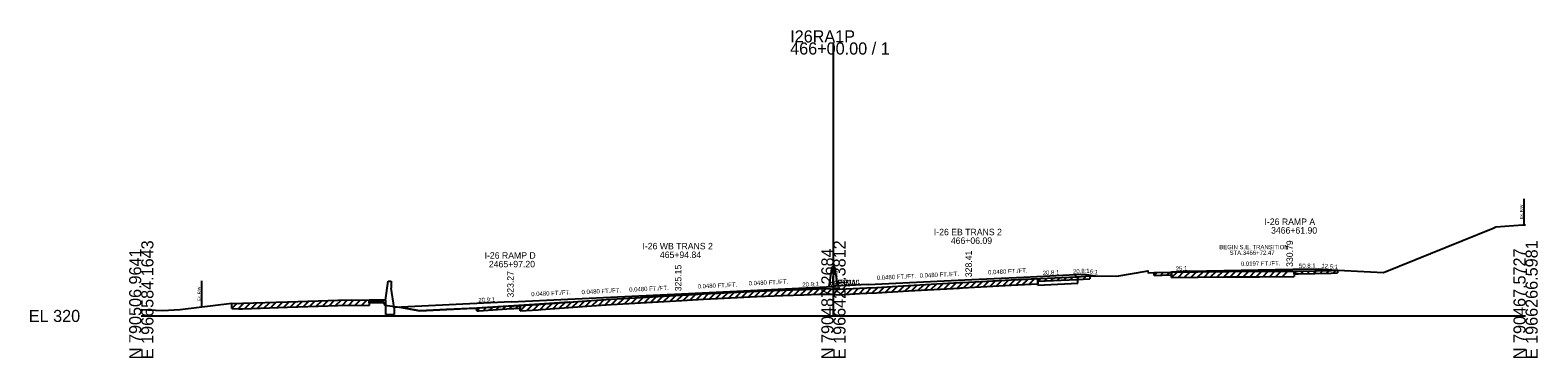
# Model space of a CAD drawing. Extents: x -44 to 4323, y -10 to 9601.
# Drawn here: x 3974.3 to 4322.8, y 4490.3 to 4566.1 of the extents above; entities that cross this region are included whole.
import ezdxf

# ---------------------------------------------------------------- set-up
doc = ezdxf.new("R2010")
doc.units = 0
for name, color, linetype in [('1', 7, 'Continuous'), ('DateStamp', 7, 'Continuous'), ('NotForConst', 7, 'Continuous'), ('QCQA', 7, 'Continuous'), ('RD_SHT_Bndy', 7, 'Continuous'), ('RD_SHT_Iplotshp', 7, 'Continuous'), ('RD_SHT_TX', 7, 'Continuous'), ('RD_XS_ExGround', 7, 'Continuous'), ('RD_XS_ExPaveRet', 7, 'Continuous'), ('RD_XS_MatchLine', 7, 'Continuous'), ('RD_XS_MedBWall', 7, 'Continuous'), ('RD_XS_Misc_Line', 7, 'Continuous'), ('RD_XS_Pave', 7, 'Continuous'), ('RD_XS_PaveOvlay', 7, 'Continuous'), ('RD_XS_PaveShd', 7, 'Continuous'), ('RD_XS_TX_Elev_PR', 7, 'Continuous'), ('RD_XS_TX_Profile', 7, 'Continuous'), ('RD_XS_TX_ShdSlope', 7, 'Continuous'), ('RD_XS_TX_Slope', 7, 'Continuous'), ('seal', 7, 'Continuous'), ('TR SN EXTRUDED PANEL SIGNS - GROUND MOUNTED', 7, 'Continuous')]:
    doc.layers.add(name, color=color, linetype=linetype)

msp = doc.modelspace()

# ---------------------------------------------------------------- linework, layer by layer
at = {"layer": 'DateStamp'}
msp.add_lwpolyline([(4000, 4501.48), (4004.93, 4501.29), (4008.98, 4501.5), (4020.9, 4502.96), (4022.54, 4502.9), (4023.4, 4502.92), (4033.79, 4503.26), (4040.87, 4503.5), (4045.42, 4503.65), (4048.7, 4503.71), (4052.67, 4503.67), (4052.81, 4503.38), (4053.89, 4503.38), (4055.81, 4503.38), (4056.28, 4502.5), (4059.72, 4502.01), (4064.36, 4501.2), (4076.82, 4501.77), (4077.57, 4501.81), (4077.99, 4501.84), (4085.55, 4502.33), (4086.14, 4502.37), (4091.71, 4502.66), (4092.46, 4502.72), (4104.11, 4503.6), (4108.61, 4503.86), (4116.78, 4504.33), (4124.99, 4504.81), (4129.94, 4505.1), (4133.18, 4505.27), (4142.32, 4505.76), (4148.34, 4505.96), (4153.18, 4506.13), (4156.64, 4506.25), (4158.63, 4506.32), (4160, 4506.23), (4160.47, 4506.2), (4161.4, 4506.16), (4166.11, 4506.41), (4167.71, 4506.49), (4169.93, 4506.61), (4177.32, 4507.04), (4189.15, 4507.7), (4189.54, 4507.72), (4189.86, 4507.74), (4201.12, 4508.35), (4216.25, 4509.08), (4219.26, 4509.24), (4220.2, 4509.24), (4225.54, 4509.22), (4232.29, 4510.35), (4232.65, 4510.4), (4232.75, 4509.95), (4234.16, 4510.02), (4237.94, 4510.15), (4250.58, 4510.3), (4251.4, 4510.31), (4258.46, 4510.33), (4267.49, 4510.35), (4275.04, 4510.53), (4276.5, 4510.56), (4278.11, 4510.49), (4287.16, 4510.04), (4312.48, 4520.33), (4313.09, 4520.58), (4319.34, 4521.07), (4320, 4521.09)], dxfattribs=at)
at = {"layer": 'NotForConst'}
for p, q in [((4234.16, 4509.39), (4234.81, 4510.04)), ((4235.66, 4509.44), (4236.31, 4510.09)), ((4237.16, 4509.5), (4237.81, 4510.14)), ((4238.16, 4508.9), (4239.43, 4510.16)), ((4239.67, 4508.92), (4240.94, 4510.18)), ((4241.17, 4508.94), (4242.45, 4510.2)), ((4242.68, 4508.96), (4243.95, 4510.22)), ((4244.19, 4508.97), (4245.46, 4510.24)), ((4245.7, 4508.99), (4246.97, 4510.26)), ((4247.2, 4509.01), (4248.48, 4510.28)), ((4248.71, 4509.03), (4249.98, 4510.3)), ((4250.22, 4509.05), (4251.49, 4510.31)), ((4251.73, 4509.07), (4252.99, 4510.32)), ((4253.23, 4509.07), (4254.49, 4510.32)), ((4254.74, 4509.07), (4256, 4510.32)), ((4256.25, 4509.07), (4257.51, 4510.33)), ((4257.76, 4509.08), (4259.02, 4510.33)), ((4259.26, 4509.08), (4260.52, 4510.33)), ((4260.77, 4509.08), (4262.03, 4510.34)), ((4262.28, 4509.09), (4263.54, 4510.34)), ((4263.79, 4509.09), (4265.05, 4510.34)), ((4266.5, 4509.72), (4267.12, 4510.35)), ((4268, 4509.74), (4268.64, 4510.38)), ((4269.5, 4509.77), (4270.14, 4510.41)), ((4271, 4509.81), (4271.64, 4510.45)), ((4272.5, 4509.84), (4273.14, 4510.48)), ((4274, 4509.88), (4274.64, 4510.52)), ((4275.5, 4509.91), (4276.15, 4510.55)), ((4167.48, 4505.23), (4168.81, 4506.55)), ((4168.99, 4505.31), (4170.32, 4506.64)), ((4170.49, 4505.4), (4171.83, 4506.72)), ((4172, 4505.48), (4173.33, 4506.81)), ((4173.51, 4505.57), (4174.84, 4506.89)), ((4175.02, 4505.65), (4176.35, 4506.98)), ((4176.52, 4505.74), (4177.86, 4507.07)), ((4178.03, 4505.83), (4179.36, 4507.15)), ((4179.54, 4505.91), (4180.87, 4507.23)), ((4181.05, 4505.99), (4182.38, 4507.32)), ((4182.55, 4506.08), (4183.88, 4507.4)), ((4184.06, 4506.16), (4185.39, 4507.49)), ((4185.57, 4506.25), (4186.9, 4507.57)), ((4187.08, 4506.33), (4188.41, 4507.66)), ((4188.58, 4506.42), (4189.91, 4507.74)), ((4190.09, 4506.5), (4191.42, 4507.82)), ((4191.6, 4506.58), (4192.93, 4507.9)), ((4193.11, 4506.66), (4194.43, 4507.98)), ((4194.61, 4506.74), (4195.94, 4508.07)), ((4196.12, 4506.83), (4197.45, 4508.15)), ((4197.63, 4506.91), (4198.96, 4508.23)), ((4199.14, 4506.99), (4200.46, 4508.31)), ((4200.64, 4507.07), (4201.97, 4508.39)), ((4202.15, 4507.15), (4203.47, 4508.46)), ((4203.66, 4507.22), (4204.98, 4508.53)), ((4205.17, 4507.29), (4206.49, 4508.61)), ((4207.26, 4508.02), (4207.92, 4508.68)), ((4208.76, 4508.09), (4209.42, 4508.75)), ((4210.26, 4508.17), (4210.92, 4508.82)), ((4211.76, 4508.24), (4212.42, 4508.9)), ((4213.26, 4508.31), (4213.92, 4508.97)), ((4214.76, 4508.39), (4215.42, 4509.04)), ((4216.26, 4508.46), (4216.92, 4509.12)), ((4217.77, 4508.53), (4218.43, 4509.19)), ((4026.9, 4501.79), (4028.2, 4503.08)), ((4028.4, 4501.84), (4029.7, 4503.13)), ((4029.9, 4501.89), (4031.2, 4503.18)), ((4031.41, 4501.93), (4032.7, 4503.23)), ((4032.91, 4501.98), (4034.2, 4503.28)), ((4034.41, 4502.03), (4035.7, 4503.33)), ((4035.91, 4502.08), (4037.2, 4503.38)), ((4037.41, 4502.14), (4038.7, 4503.43)), ((4038.91, 4502.19), (4040.2, 4503.48)), ((4040.41, 4502.24), (4041.7, 4503.53)), ((4041.91, 4502.29), (4043.2, 4503.58)), ((4043.41, 4502.34), (4044.7, 4503.63)), ((4044.91, 4502.39), (4046.19, 4503.67)), ((4046.41, 4502.42), (4047.68, 4503.69)), ((4047.91, 4502.45), (4049.17, 4503.71)), ((4049.41, 4502.46), (4050.65, 4503.69)), ((4050.91, 4502.44), (4052.15, 4503.68)), ((4096.63, 4501.78), (4097.99, 4503.14)), ((4098.13, 4501.9), (4099.49, 4503.25)), ((4099.64, 4502.01), (4101, 4503.37)), ((4101.15, 4502.13), (4102.51, 4503.48)), ((4102.66, 4502.24), (4104.02, 4503.6)), ((4104.16, 4502.36), (4105.5, 4503.68)), ((4105.67, 4502.44), (4107, 4503.77)), ((4107.18, 4502.53), (4108.51, 4503.86)), ((4108.69, 4502.62), (4110.02, 4503.94)), ((4110.19, 4502.7), (4111.53, 4504.03)), ((4111.7, 4502.79), (4113.04, 4504.12)), ((4113.21, 4502.88), (4114.54, 4504.21)), ((4114.72, 4502.97), (4116.05, 4504.29)), ((4116.22, 4503.05), (4117.56, 4504.38)), ((4117.73, 4503.14), (4119.07, 4504.47)), ((4119.24, 4503.23), (4120.57, 4504.55)), ((4120.75, 4503.31), (4122.08, 4504.64)), ((4122.25, 4503.4), (4123.59, 4504.73)), ((4123.76, 4503.49), (4125.1, 4504.82)), ((4125.27, 4503.58), (4126.6, 4504.9)), ((4126.78, 4503.66), (4128.11, 4504.99)), ((4128.28, 4503.75), (4129.62, 4505.08)), ((4129.79, 4503.84), (4131.12, 4505.16)), ((4131.3, 4503.92), (4132.63, 4505.24)), ((4132.81, 4504), (4134.13, 4505.32)), ((4134.31, 4504.08), (4135.64, 4505.4)), ((4135.82, 4504.16), (4137.15, 4505.49)), ((4137.33, 4504.24), (4138.66, 4505.57)), ((4138.84, 4504.33), (4140.16, 4505.65)), ((4140.34, 4504.41), (4141.67, 4505.73)), ((4141.85, 4504.49), (4143.16, 4505.79)), ((4143.36, 4504.55), (4144.66, 4505.84)), ((4144.87, 4504.6), (4146.17, 4505.89)), ((4146.37, 4504.65), (4147.67, 4505.94)), ((4147.88, 4504.7), (4149.18, 4505.99)), ((4149.39, 4504.75), (4150.69, 4506.04)), ((4150.9, 4504.8), (4152.2, 4506.1)), ((4152.4, 4504.85), (4153.71, 4506.15)), ((4153.91, 4504.91), (4155.21, 4506.2)), ((4155.42, 4504.96), (4156.72, 4506.26)), ((4156.93, 4505.01), (4158.22, 4506.3)), ((4158.43, 4505.06), (4159.63, 4506.25)), ((4159.94, 4504.99), (4161.13, 4506.17)), ((4161.45, 4504.91), (4162.78, 4506.23)), ((4162.96, 4504.99), (4164.28, 4506.31)), ((4164.46, 4505.07), (4165.79, 4506.39)), ((4165.97, 4505.15), (4167.29, 4506.47)), ((4020.9, 4501.71), (4022.11, 4502.91)), ((4022.4, 4501.65), (4023.68, 4502.93)), ((4023.9, 4501.69), (4025.2, 4502.98)), ((4025.4, 4501.74), (4026.7, 4503.03)), ((4077.57, 4501.19), (4078.24, 4501.85)), ((4079.07, 4501.28), (4079.74, 4501.95)), ((4080.57, 4501.38), (4081.24, 4502.05)), ((4082.07, 4501.48), (4082.74, 4502.15)), ((4083.57, 4501.58), (4084.24, 4502.25)), ((4085.07, 4501.68), (4085.74, 4502.34)), ((4086.58, 4501.77), (4087.24, 4502.43)), ((4087.58, 4501.2), (4088.91, 4502.51)), ((4089.09, 4501.27), (4090.41, 4502.59)), ((4090.6, 4501.35), (4091.93, 4502.68)), ((4092.1, 4501.44), (4093.46, 4502.79)), ((4093.61, 4501.55), (4094.97, 4502.91)), ((4095.12, 4501.67), (4096.48, 4503.02))]:
    msp.add_line(p, q, dxfattribs=at)
at = {"layer": 'QCQA'}
for p, q in [((4167.71, 4506.49), (4169.93, 4506.61)), ((4169.93, 4506.61), (4177.32, 4507.04)), ((4177.32, 4507.04), (4189.15, 4507.7)), ((4189.15, 4507.7), (4189.54, 4507.72)), ((4189.54, 4507.72), (4189.86, 4507.74)), ((4189.86, 4507.74), (4201.12, 4508.35)), ((4201.12, 4508.35), (4207.26, 4508.65)), ((4099, 4503.22), (4092.09, 4502.69)), ((4099, 4503.22), (4104.11, 4503.6)), ((4104.11, 4503.6), (4108.61, 4503.86)), ((4108.61, 4503.86), (4116.78, 4504.33)), ((4116.78, 4504.33), (4124.99, 4504.81)), ((4124.99, 4504.81), (4129.94, 4505.1)), ((4129.94, 4505.1), (4133.18, 4505.27)), ((4133.18, 4505.27), (4142.32, 4505.76)), ((4142.32, 4505.76), (4148.34, 4505.96)), ((4148.34, 4505.96), (4153.18, 4506.13)), ((4153.18, 4506.13), (4156.64, 4506.25)), ((4156.64, 4506.25), (4158.63, 4506.32)), ((4158.63, 4506.32), (4160, 4506.23)), ((4160, 4506.23), (4160.47, 4506.2)), ((4160.47, 4506.2), (4161.4, 4506.16)), ((4161.4, 4506.16), (4166.11, 4506.41)), ((4166.11, 4506.41), (4167.71, 4506.49)), ((4064.36, 4501.2), (4059.6, 4502.02)), ((4070.59, 4501.48), (4064.36, 4501.2)), ((4077.57, 4501.82), (4070.59, 4501.48)), ((4086.14, 4502.37), (4077.57, 4501.82)), ((4092.09, 4502.69), (4086.14, 4502.37))]:
    msp.add_line(p, q, dxfattribs=at)
at = {"layer": 'RD_SHT_Bndy'}
for p, q in [((4160, 4500), (4160, 4563.26)), ((4000, 4500), (4160, 4500)), ((4160, 4500), (4320, 4500))]:
    msp.add_line(p, q, dxfattribs=at)
at = {"layer": 'RD_SHT_Iplotshp'}
for p, q in [((4234.16, 4509.39), (4234.16, 4510.02)), ((4238.16, 4508.9), (4238.16, 4510.15)), ((4238.16, 4510.15), (4238.16, 4509.52)), ((4266.5, 4510.35), (4266.5, 4509.1)), ((4266.5, 4509.72), (4266.5, 4510.35)), ((4276.5, 4510.56), (4276.5, 4509.94)), ((4189.86, 4506.49), (4201.12, 4507.1)), ((4201.12, 4507.1), (4207.26, 4507.4)), ((4207.26, 4508.65), (4207.26, 4507.4)), ((4207.26, 4508.02), (4207.26, 4508.65)), ((4207.26, 4508.02), (4216.25, 4508.46)), ((4216.25, 4508.46), (4219.26, 4508.61)), ((4219.26, 4509.24), (4219.26, 4508.61)), ((4234.16, 4509.39), (4237.94, 4509.52)), ((4237.94, 4509.52), (4238.16, 4509.52)), ((4238.16, 4508.9), (4250.58, 4509.05)), ((4250.58, 4509.05), (4251.4, 4509.06)), ((4251.4, 4509.06), (4258.46, 4509.08)), ((4258.46, 4509.08), (4266.5, 4509.1)), ((4266.5, 4509.72), (4267.49, 4509.72)), ((4267.49, 4509.72), (4275.04, 4509.9)), ((4275.04, 4509.9), (4276.5, 4509.94)), ((4052.67, 4503.67), (4052.67, 4502.42)), ((4108.61, 4502.61), (4116.78, 4503.08)), ((4116.78, 4503.08), (4124.99, 4503.56)), ((4124.99, 4503.56), (4129.94, 4503.85)), ((4129.94, 4503.85), (4133.18, 4504.02)), ((4133.18, 4504.02), (4142.32, 4504.51)), ((4142.32, 4504.51), (4148.34, 4504.71)), ((4148.34, 4504.71), (4153.18, 4504.88)), ((4153.18, 4504.88), (4156.64, 4505)), ((4156.64, 4505), (4158.63, 4505.07)), ((4158.63, 4505.07), (4160, 4504.98)), ((4160, 4504.98), (4160.47, 4504.95)), ((4160.47, 4504.95), (4161.4, 4504.91)), ((4161.4, 4504.91), (4166.11, 4505.16)), ((4166.11, 4505.16), (4167.71, 4505.24)), ((4167.71, 4505.24), (4169.93, 4505.36)), ((4169.93, 4505.36), (4177.32, 4505.79)), ((4177.32, 4505.79), (4189.15, 4506.45)), ((4189.15, 4506.45), (4189.54, 4506.47)), ((4189.54, 4506.47), (4189.86, 4506.49)), ((4020.9, 4501.71), (4020.9, 4502.96)), ((4020.9, 4501.71), (4022.54, 4501.65)), ((4022.54, 4501.65), (4023.4, 4501.67)), ((4023.4, 4501.67), (4033.79, 4502.01)), ((4033.79, 4502.01), (4040.87, 4502.25)), ((4040.87, 4502.25), (4045.42, 4502.4)), ((4045.42, 4502.4), (4048.7, 4502.46)), ((4048.7, 4502.46), (4052.67, 4502.42)), ((4077.57, 4501.19), (4077.57, 4501.81)), ((4077.57, 4501.19), (4077.99, 4501.21)), ((4077.99, 4501.21), (4085.55, 4501.71)), ((4085.55, 4501.71), (4086.14, 4501.75)), ((4086.14, 4501.75), (4087.58, 4501.82)), ((4087.58, 4501.2), (4087.58, 4502.45)), ((4087.58, 4502.45), (4087.58, 4501.82)), ((4087.58, 4501.2), (4091.71, 4501.41)), ((4091.71, 4501.41), (4092.46, 4501.47)), ((4092.46, 4501.47), (4104.11, 4502.35)), ((4104.11, 4502.35), (4108.61, 4502.61))]:
    msp.add_line(p, q, dxfattribs=at)
at = {"layer": 'RD_XS_ExPaveRet'}
msp.add_line((4056.43, 4503.62), (4056.43, 4500.34), dxfattribs=at)
at = {"layer": 'RD_XS_Misc_Line'}
for p, q in [((4238.22, 4510.15), (4238.22, 4510.16)), ((4272.23, 4510.46), (4272.23, 4510.91)), ((4207.26, 4507.1), (4207.26, 4508.65)), ((4207.26, 4507.1), (4216.5, 4507.55)), ((4216, 4509), (4216, 4509.56)), ((4216, 4509), (4216.5, 4509.03)), ((4216.5, 4507.55), (4216.5, 4509.03)), ((4052.67, 4503.01), (4052.67, 4503.67)), ((4056.43, 4502.95), (4052.67, 4503.01))]:
    msp.add_line(p, q, dxfattribs=at)
at = {"layer": 'RD_XS_Pave'}
for p, q in [((4276.23, 4510.59), (4276.5, 4510.56)), ((4218, 4509.66), (4220.55, 4509.24))]:
    msp.add_line(p, q, dxfattribs=at)
at = {"layer": 'RD_XS_PaveOvlay'}
for p, q in [((4319.62, 4527.08), (4319.62, 4521.08)), ((4013.93, 4508.1), (4013.93, 4502.1))]:
    msp.add_line(p, q, dxfattribs=at)
at = {"layer": 'RD_XS_PaveShd'}
for p, q in [((4238.22, 4510.16), (4238.13, 4510.15)), ((4272.23, 4510.91), (4276.23, 4510.59)), ((4216, 4509.56), (4218, 4509.66))]:
    msp.add_line(p, q, dxfattribs=at)
at = {"layer": 'RD_XS_TX_Elev_PR'}
for p, q in [((4242.22, 4510.32), (4238.22, 4510.16)), ((4266.23, 4510.79), (4272.23, 4510.91)), ((4124.39, 4509.88), (4124.39, 4509.91)), ((4148.86, 4506.31), (4160, 4506.84)), ((4168, 4507.26), (4160, 4506.88)), ((4160, 4506.84), (4160, 4506.88)), ((4204, 4508.99), (4216, 4509.56)), ((4056.43, 4503.62), (4052.67, 4503.67)), ((4056.43, 4503.62), (4056.43, 4502.95)), ((4085.54, 4503.27), (4058.43, 4501.97))]:
    msp.add_line(p, q, dxfattribs=at)
at = {"layer": 'RD_XS_TX_ShdSlope'}
for p, q in [((4159, 4506.79), (4159.67, 4511.34)), ((4159.67, 4511.38), (4160.33, 4511.38)), ((4159.67, 4511.34), (4159.67, 4511.38)), ((4161, 4506.92), (4160.33, 4511.38)), ((4056.43, 4503.62), (4057.1, 4508.07)), ((4057.1, 4508.07), (4057.77, 4508.07)), ((4057.77, 4508.07), (4057.77, 4506.42)), ((4058.43, 4501.97), (4057.77, 4506.42)), ((4056.43, 4500.34), (4058.43, 4500.34)), ((4058.43, 4501.97), (4058.43, 4500.34))]:
    msp.add_line(p, q, dxfattribs=at)
at = {"layer": 'RD_XS_TX_Slope'}
for p, q in [((4242.22, 4510.32), (4266.23, 4510.79)), ((4168, 4507.26), (4192, 4508.41)), ((4192, 4508.41), (4204, 4508.99)), ((4085.54, 4503.27), (4124.86, 4505.15)), ((4124.86, 4505.15), (4148.86, 4506.31))]:
    msp.add_line(p, q, dxfattribs=at)

# ---------------------------------------------------------------- texts
at = {"layer": '1'}
for s, p in [('I-26 RAMP A', (4259.66, 4521.04)), ('3466+61.90', (4261.17, 4519.04)), ('I-26 EB TRANS 2', (4183.22, 4518.66)), ('466+06.09', (4187.14, 4516.66)), ('I-26 RAMP D', (4079.36, 4513.24)), ('I-26 WB TRANS 2', (4115.85, 4515.4)), ('465+94.84', (4119.88, 4513.4)), ('2465+97.20', (4080.36, 4511.24))]:
    msp.add_text(s, height=1.5, dxfattribs=at).set_placement(p)
at = {"layer": 'RD_SHT_Bndy'}
for s, p in [('I26RA1P', (4150, 4563.26)), ('466+00.00 / 1', (4150, 4560.46)), ('EL 320', (3974, 4498.6))]:
    msp.add_text(s, height=2.8, dxfattribs=at).set_placement(p)
for s, p in [('E 1966584.1643', (4002.8, 4490)), ('E 1966425.3812', (4162.8, 4490)), ('E 1966266.5981', (4322.8, 4490)), ('N 790506.9641', (4000, 4490)), ('N 790487.2684', (4160, 4490)), ('N 790467.5727', (4320, 4490))]:
    msp.add_text(s, height=2.8, rotation=90, dxfattribs=at).set_placement(p)
at = {"layer": 'RD_SHT_TX'}
msp.add_text('326.23', height=1, rotation=90, dxfattribs=at).set_placement((4161, 4506.23))
at = {"layer": 'RD_XS_ExGround'}
for s, rotation, p in [('20.8:1', 2.7481, (4208.41, 4509.45)), ('20.9:1', 2.7458, (4152.84, 4506.75)), ('20.8:1', 2.7481, (4162.41, 4507.24)), ('20.9:1', 2.7458, (4077.95, 4503.15))]:
    msp.add_text(s, height=1, rotation=rotation, dxfattribs=at).set_placement(p)
at = {"layer": 'RD_XS_MatchLine'}
for s, p in [('BEGIN S.E. TRANSITION', (4249.19, 4515.43)), ('STA.3466+72.47', (4251.58, 4514.12))]:
    msp.add_text(s, height=1, dxfattribs=at).set_placement(p)
at = {"layer": 'RD_XS_MedBWall'}
for s, rotation, p in [('20.8:1', 2.7481, (4215.41, 4509.79)), ('12.5:1', 355.4269, (4272.77, 4511.11))]:
    msp.add_text(s, height=1, rotation=rotation, dxfattribs=at).set_placement(p)
at = {"layer": 'RD_XS_PaveOvlay'}
for p in [(4319.37, 4522.46), (4013.68, 4503.49)]:
    msp.add_text('Ex. R/W ', height=0.65, rotation=90, dxfattribs=at).set_placement(p)
at = {"layer": 'RD_XS_TX_Profile'}
for s, p in [('WBW', (4159, 4506.79)), ('EBW', (4161, 4506.92))]:
    msp.add_text(s, height=1.5, dxfattribs=at).set_placement(p)
at = {"layer": 'seal'}
for s, p in [(' 330.79', (4266.23, 4510.79)), (' 328.41', (4192, 4508.41)), ('323.27', (4086.08, 4504.25)), (' 325.15', (4124.86, 4505.15))]:
    msp.add_text(s, height=1.5, rotation=90, dxfattribs=at).set_placement(p)
at = {"layer": 'TR SN EXTRUDED PANEL SIGNS - GROUND MOUNTED'}
for s, rotation, p in [('0.0480 FT./FT.', 2.7481, (4179.95, 4508.83)), ('0.0480 FT./FT.', 2.7481, (4195.77, 4509.59)), ('6:1', 350.5377, (4219.16, 4509.87)), ('25:1', 2.2902, (4239.16, 4510.44)), ('0.0197 FT./FT.', 1.127, (4254.2, 4511.55)), ('50.8:1', 1.127, (4267.64, 4511.07)), ('0.0480 FT./FT.', 2.7458, (4112.81, 4505.58)), ('0.0480 FT./FT.', 2.7458, (4128.63, 4506.34)), ('0.0480 FT./FT.', 2.75, (4140.42, 4507.04)), ('0.0480 FT./FT.', 2.7481, (4170.05, 4508.32)), ('0.0480 FT./FT.', 2.75, (4090.17, 4504.54)), ('0.0480 FT./FT.', 2.7458, (4101.8, 4505.02))]:
    msp.add_text(s, height=1, rotation=rotation, dxfattribs=at).set_placement(p)

doc.saveas('drawing.dxf')
